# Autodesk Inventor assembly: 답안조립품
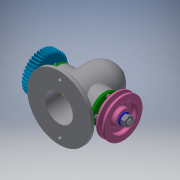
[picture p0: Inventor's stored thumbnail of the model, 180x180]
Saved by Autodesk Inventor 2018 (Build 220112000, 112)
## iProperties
Created: 2019-11
Part Number: 답안조립품
Document SubType Name: Assembly
Designer: Administrator
Author: Administrator
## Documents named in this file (14)
- C:\Users\Administrator\Desktop\491104V1058\답안조립품.iam
- C:\Users\Administrator\Desktop\491104V1058\본체.ipt
- C:\Users\Administrator\Desktop\491104V1058\축.ipt
- C:\Users\Administrator\Desktop\491104V1058\베어링 6203.ipt
- C:\Users\Administrator\Desktop\491104V1058\오일 실 26 38 8.ipt
- C:\Users\Administrator\Desktop\491104V1058\커버.ipt
- C:\Users\Administrator\Desktop\491104V1058\부시.ipt
- C:\Users\Administrator\Desktop\491104V1058\볼트 M4.ipt
- C:\Users\Administrator\Desktop\491104V1058\키 5x5x12.ipt
- C:\Users\Administrator\Desktop\491104V1058\V-벨트풀리.ipt
- V-벨트풀리.ipt
- C:\Users\Administrator\Desktop\491104V1058\스퍼기어.ipt
- C:\Users\Administrator\Desktop\491104V1058\와셔 12x24.ipt
- C:\Users\Administrator\Desktop\491104V1058\너트 M12x1.25.ipt
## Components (1 placed, 1 different names)
1. V-벨트풀리:1
